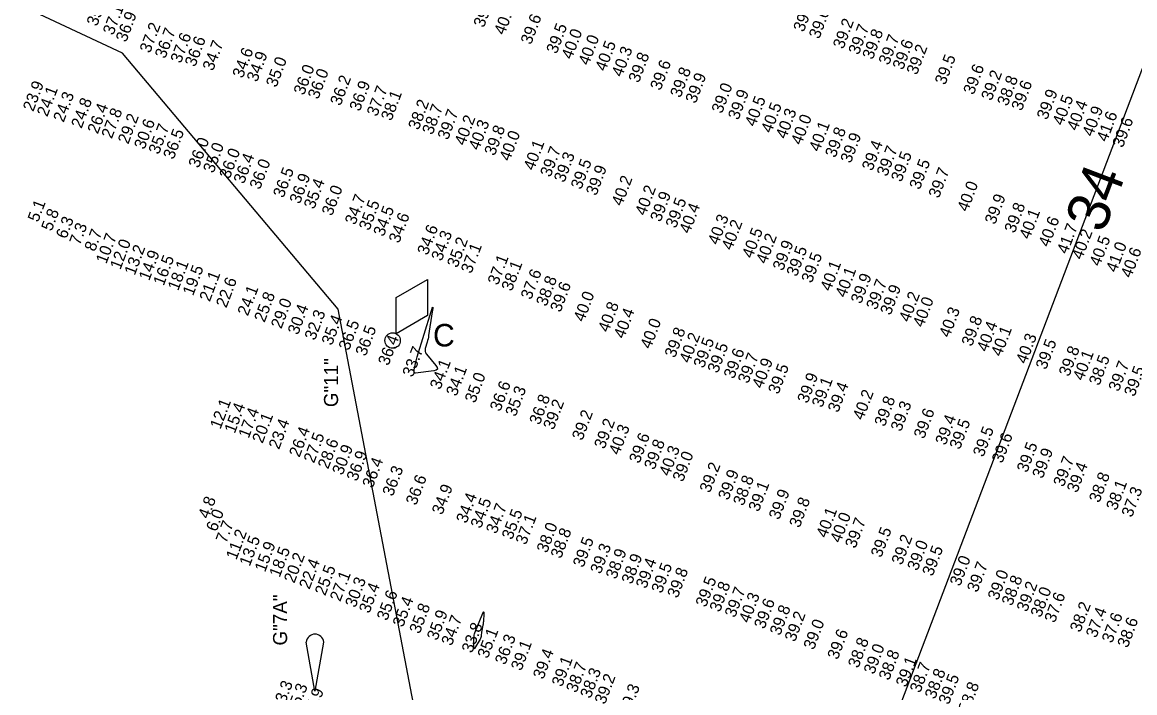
# Model space of a CAD drawing. Extents: x 510771 to 514171, y 1309813 to 1314213.
# Drawn here: x 511955 to 512904, y 1310850 to 1311422 of the extents above; entities that cross this region are included whole.
import ezdxf

# ---------------------------------------------------------------- set-up
doc = ezdxf.new("R2010")
doc.units = 0
for name, color, linetype in [('C-CHAN-CNTR', 7, 'Continuous'), ('C-CHAN-WIDE', 7, 'Continuous'), ('V-CHAN-NAID', 7, 'Continuous'), ('V-CHAN-TEXT', 7, 'Continuous'), ('V-TOPO-MAJR', 7, 'Continuous'), ('V-TOPO-SOUN', 7, 'Continuous')]:
    doc.layers.add(name, color=color, linetype=linetype)

msp = doc.modelspace()

# ---------------------------------------------------------------- linework, layer by layer
at = {"layer": 'C-CHAN-CNTR'}
msp.add_line((512571.8, 1310492.84), (513203.85, 1312154.97), dxfattribs=at)
at = {"layer": 'C-CHAN-WIDE'}
for p, q in [((512040.63, 1311395.58), (511536.45, 1311632.64)), ((512224.55, 1311177.34), (512040.63, 1311395.58)), ((512295.17, 1310807.21), (512224.55, 1311177.34))]:
    msp.add_line(p, q, dxfattribs=at)
at = {"layer": 'V-CHAN-NAID'}
for p, q in [((512274.08, 1311187.33), (512300.8, 1311202.76)), ((512300.8, 1311202.76), (512300.8, 1311171.9)), ((512274.08, 1311156.46), (512274.08, 1311187.33)), ((512300.8, 1311171.9), (512274.08, 1311156.46)), ((512204.75, 1310851.65), (512197.35, 1310893.6)), ((512212.14, 1310893.6), (512204.75, 1310851.65))]:
    msp.add_line(p, q, dxfattribs=at)
msp.add_circle((512270.91, 1311150.67), 6.6, dxfattribs=at)
msp.add_arc((512204.75, 1310893), 7.42, 4.64421, 175.35452, dxfattribs=at)
at = {"layer": 'V-TOPO-MAJR'}
for points in [[(512289.21, 1311125.08), (512289.22, 1311125.35), (512289.27, 1311125.63), (512290.76, 1311132.13), (512291.04, 1311133.3), (512291.34, 1311134.47), (512291.66, 1311135.63), (512292, 1311136.79), (512303.69, 1311175.4), (512304.61, 1311178.18), (512305.09, 1311179.06), (512305.14, 1311178.05), (512304.77, 1311175.15), (512301.65, 1311154.86), (512301.41, 1311153.47), (512301.13, 1311152.08), (512300.79, 1311150.71), (512300.42, 1311149.34), (512298.81, 1311143.91), (512298.57, 1311142.58), (512298.66, 1311141.33), (512299.08, 1311140.14), (512299.82, 1311139.02), (512307.92, 1311129.33), (512309.05, 1311127.56), (512309.12, 1311126.22), (512308.14, 1311125.29), (512306.11, 1311124.78), (512290.37, 1311122.95), (512290.11, 1311122.96), (512289.9, 1311123.04), (512289.74, 1311123.2), (512289.63, 1311123.44), (512289.3, 1311124.53), (512289.24, 1311124.8)], [(512348.16, 1310909.57), (512348.05, 1310908.84), (512347.91, 1310908.12), (512347.29, 1310905.23), (512347.15, 1310904.51), (512347.02, 1310903.78), (512346.91, 1310903.05), (512346.81, 1310902.32), (512346.44, 1310899.05), (512346.31, 1310898.28), (512346.11, 1310897.53), (512345.82, 1310896.8), (512345.46, 1310896.11), (512340.79, 1310888.09), (512340.6, 1310887.84), (512340.46, 1310887.77), (512340.37, 1310887.89), (512340.31, 1310888.2), (512340.19, 1310889.83), (512340.16, 1310890.24), (512340.14, 1310890.64), (512340.14, 1310891.05), (512340.14, 1310891.46), (512340.28, 1310897.33), (512340.36, 1310898.43), (512340.53, 1310899.52), (512340.79, 1310900.58), (512341.16, 1310901.63), (512347.76, 1310918.15), (512348.21, 1310919.12), (512348.5, 1310919.41), (512348.65, 1310919.02), (512348.66, 1310917.96), (512348.3, 1310911.04), (512348.25, 1310910.3)]]:
    msp.add_lwpolyline(points, close=True, dxfattribs=at)

# ---------------------------------------------------------------- texts
at = {"layer": 'V-CHAN-NAID'}
for s, height, rotation, p in [('C', 19.2, 0.00274, (512305.37, 1311145.61)), ('G"11"', 12, 90, (512224.42, 1311093.92)), ('G"7A"', 12, 90, (512180.97, 1310890.68))]:
    msp.add_text(s, height=height, rotation=rotation, dxfattribs=at).set_placement(p)
at = {"layer": 'V-CHAN-TEXT'}
msp.add_text('34', height=36, rotation=69.17989, dxfattribs=at).set_placement((512876.96, 1311241.2))
at = {"layer": 'V-TOPO-SOUN'}
for s, p in [('35.9 ', (512018.87, 1311418.05)), ('39.4 ', (512348.69, 1311416.85)), ('37.1 ', (512032.73, 1311410.45)), ('40.0 ', (512366.23, 1311410.57)), ('39.2 ', (512621.42, 1311413.09)), ('39.6 ', (512634.68, 1311407.22)), ('36.9 ', (512043.73, 1311404.45)), ('39.6 ', (512388.94, 1311402.35)), ('39.2 ', (512655.22, 1311398.6)), ('37.2 ', (512064.09, 1311395.15)), ('36.7 ', (512077.02, 1311390.43)), ('37.6 ', (512090.34, 1311386.47)), ('39.5 ', (512410.81, 1311394.43)), ('40.0 ', (512423.7, 1311389.77)), ('39.7 ', (512668.35, 1311393.66)), ('39.8 ', (512680.27, 1311389.6)), ('36.6 ', (512102.58, 1311383.43)), ('34.7 ', (512117.73, 1311379.88)), ('40.0 ', (512438.09, 1311384.68)), ('40.5 ', (512452.43, 1311379.61)), ('39.7 ', (512694.1, 1311384.9)), ('39.6 ', (512706.04, 1311380.76)), ('34.6 ', (512143.16, 1311373.72)), ('34.9 ', (512155.33, 1311370.47)), ('40.3 ', (512466.48, 1311374.76)), ('39.8 ', (512480.84, 1311369.78)), ('39.2 ', (512717.94, 1311376.49)), ('39.5 ', (512742.1, 1311367.93)), ('35.0 ', (512171.78, 1311365.89)), ('36.0 ', (512195.35, 1311359.27)), ('39.6 ', (512499.36, 1311363.27)), ('39.6 ', (512766.35, 1311359.61)), ('36.0 ', (512207.45, 1311355.78)), ('36.2 ', (512226.51, 1311350.24)), ('39.8 ', (512516.41, 1311357.08)), ('39.9 ', (512529.4, 1311352.2)), ('39.2 ', (512781.58, 1311354.53)), ('38.8 ', (512795.24, 1311349.95)), ('23.9 ', (511964.54, 1311345.34)), ('24.1 ', (511976.47, 1311340.89)), ('36.9 ', (512242.91, 1311345.49)), ('37.7 ', (512257.7, 1311341.12)), ('39.0 ', (512551.72, 1311343.62)), ('39.6 ', (512807.32, 1311345.86)), ('24.3 ', (511990.39, 1311336.12)), ('24.8 ', (512005.68, 1311330.96)), ('38.1 ', (512269.84, 1311337.29)), ('38.2 ', (512293.05, 1311329.56)), ('39.9 ', (512565.75, 1311338.1)), ('40.5 ', (512580.06, 1311332.38)), ('39.9 ', (512829.01, 1311338.23)), ('40.5 ', (512842.4, 1311333.38)), ('26.4 ', (512019.54, 1311326.25)), ('27.8 ', (512031.47, 1311322.2)), ('38.7 ', (512304.94, 1311325.5)), ('39.7 ', (512318.09, 1311321.07)), ('40.5 ', (512593.81, 1311326.94)), ('40.3 ', (512606.34, 1311321.92)), ('40.4 ', (512854.66, 1311328.87)), ('40.9 ', (512867.81, 1311323.95)), ('29.2 ', (512045.51, 1311317.52)), ('30.6 ', (512059.34, 1311312.99)), ('40.2 ', (512332.49, 1311316.23)), ('40.3 ', (512344.48, 1311312.25)), ('40.0 ', (512619.36, 1311316.83)), ('41.6 ', (512880.02, 1311319.4)), ('39.6 ', (512893.52, 1311314.46)), ('35.7 ', (512071.59, 1311308.78)), ('36.5 ', (512084.13, 1311304.48)), ('39.8 ', (512357.93, 1311307.61)), ('40.0 ', (512370.72, 1311302.99)), ('40.1 ', (512634.76, 1311311.01)), ('39.8 ', (512648.52, 1311305.94)), ('39.9 ', (512661.56, 1311301.23)), ('36.0 ', (512105.65, 1311297.14)), ('35.0 ', (512118.18, 1311292.81)), ('40.1 ', (512391.33, 1311295.02)), ('39.4 ', (512679.91, 1311294.68)), ('36.0 ', (512131.98, 1311287.94)), ('36.4 ', (512144.14, 1311283.64)), ('39.7 ', (512405.54, 1311289.43)), ('39.3 ', (512417.3, 1311284.73)), ('39.7 ', (512692.54, 1311289.99)), ('39.5 ', (512704.73, 1311285.22)), ('36.0 ', (512157.76, 1311278.81)), ('39.5 ', (512431.7, 1311278.87)), ('39.9 ', (512444.59, 1311273.58)), ('39.5 ', (512720.36, 1311278.7)), ('36.5 ', (512177.82, 1311271.65)), ('36.9 ', (512191.81, 1311266.55)), ('40.2 ', (512466.45, 1311264.7)), ('39.7 ', (512736.68, 1311271.41)), ('35.4 ', (512204.05, 1311262.09)), ('36.0 ', (512219.31, 1311256.38)), ('40.2 ', (512486.47, 1311256.47)), ('40.0 ', (512761.18, 1311259.89)), ('34.7 ', (512239.05, 1311248.64)), ('35.5 ', (512251.01, 1311243.82)), ('39.9 ', (512499.37, 1311251.15)), ('39.5 ', (512512.49, 1311245.84)), ('39.9 ', (512784.65, 1311248.98)), ('5.1', (511968.66, 1311251.04)), ('5.8', (511980.2, 1311243.36)), ('34.5 ', (512263.3, 1311238.72)), ('40.4 ', (512524.16, 1311241.22)), ('39.8 ', (512801.39, 1311241.67)), ('40.1 ', (512814.02, 1311236.38)), ('6.3', (511992.71, 1311236.78)), ('34.6 ', (512276.44, 1311233.04)), ('40.3 ', (512548.52, 1311231.62)), ('40.2 ', (512560.2, 1311227.05)), ('40.6 ', (512830.46, 1311229.8)), ('7.3', (512004.21, 1311231.37)), ('8.7', (512017.02, 1311225.96)), ('10.7 ', (512026.77, 1311215.42)), ('34.6 ', (512300.77, 1311222.79)), ('34.3 ', (512312.73, 1311217.82)), ('40.5 ', (512577.63, 1311220.15)), ('40.2 ', (512589.61, 1311215.36)), ('41.7 ', (512846.18, 1311223.79)), ('40.2 ', (512858.73, 1311219.03)), ('12.0 ', (512038.81, 1311210.5)), ('35.2 ', (512326.16, 1311212.15)), ('39.9 ', (512603.79, 1311209.52)), ('40.5 ', (512873.94, 1311213.36)), ('41.0 ', (512887.99, 1311208.11)), ('13.2 ', (512051.02, 1311205.67)), ('14.9 ', (512063.35, 1311201.08)), ('16.5 ', (512075.68, 1311196.76)), ('37.1 ', (512338, 1311207.15)), ('39.5 ', (512615.53, 1311204.57)), ('39.5 ', (512628.28, 1311199.08)), ('40.6 ', (512900.58, 1311203.42)), ('18.1 ', (512088.05, 1311192.6)), ('19.5 ', (512100.77, 1311188.29)), ('37.1 ', (512360.78, 1311197.32)), ('38.1 ', (512372.54, 1311192.12)), ('40.1 ', (512644.35, 1311192.14)), ('21.1 ', (512114.99, 1311183.22)), ('22.6 ', (512129.17, 1311177.95)), ('37.6 ', (512389.01, 1311184.9)), ('38.8 ', (512402.09, 1311179.19)), ('40.1 ', (512657.18, 1311186.67)), ('39.9 ', (512670.39, 1311181.34)), ('24.1 ', (512147.49, 1311171.05)), ('39.6 ', (512414.05, 1311174.13)), ('39.7 ', (512683.54, 1311176.24)), ('39.9 ', (512695.5, 1311171.71)), ('25.8 ', (512161.74, 1311165.56)), ('29.0 ', (512176, 1311160.08)), ('40.0 ', (512434, 1311165.97)), ('40.2 ', (512711.51, 1311165.74)), ('40.0 ', (512723.31, 1311161.26)), ('30.4 ', (512190.29, 1311154.93)), ('32.3 ', (512204.68, 1311150.22)), ('40.8 ', (512454.91, 1311157.09)), ('40.4 ', (512468.27, 1311151.68)), ('40.3 ', (512745.69, 1311152.57)), ('35.4 ', (512219.17, 1311145.93)), ('36.5 ', (512233.7, 1311141.59)), ('40.0 ', (512490.91, 1311142.91)), ('39.8 ', (512764.84, 1311145.09)), ('40.4 ', (512777.85, 1311140.42)), ('36.5 ', (512248.05, 1311136.76)), ('39.8 ', (512511.7, 1311135.26)), ('40.2 ', (512524.2, 1311130.79)), ('40.1 ', (512789.93, 1311136.42)), ('40.3 ', (512811.23, 1311130.13)), ('36.4 ', (512267.34, 1311128.63)), ('39.5 ', (512536.25, 1311126.5)), ('39.5 ', (512548.21, 1311122.26)), ('39.5 ', (512828.09, 1311125.26)), ('33.7 ', (512288.09, 1311118.88)), ('39.6 ', (512562.02, 1311117.48)), ('39.7 ', (512574.09, 1311113.41)), ('39.8 ', (512847.78, 1311119.42)), ('40.1 ', (512859.76, 1311115.82)), ('38.5 ', (512873.46, 1311111.63)), ('34.1 ', (512311.56, 1311108.21)), ('40.9 ', (512586.21, 1311109.11)), ('39.5 ', (512599.89, 1311104.27)), ('39.7 ', (512890.08, 1311106.56)), ('39.5 ', (512903.44, 1311102.21)), ('34.1 ', (512325.33, 1311102.56)), ('35.0 ', (512341.28, 1311096.78)), ('39.9 ', (512624.8, 1311096.53)), ('36.6 ', (512362.68, 1311089.6)), ('35.3 ', (512375.84, 1311085.22)), ('39.1 ', (512637.19, 1311092.89)), ('39.4 ', (512650.81, 1311088.65)), ('12.1 ', (512124.09, 1311074.51)), ('36.8 ', (512396.31, 1311078.13)), ('39.2 ', (512408.18, 1311073.93)), ('40.2 ', (512672.07, 1311082.19)), ('39.8 ', (512690.54, 1311076.68)), ('15.4 ', (512136.32, 1311070.92)), ('17.4 ', (512148.21, 1311066.73)), ('39.2 ', (512432.69, 1311064.9)), ('39.3 ', (512704.41, 1311072.46)), ('39.6 ', (512724.09, 1311066.27)), ('20.1 ', (512160.04, 1311062.47)), ('23.4 ', (512174.08, 1311057.26)), ('39.2 ', (512451.58, 1311057.59)), ('39.4 ', (512742.48, 1311060.81)), ('39.5 ', (512754.56, 1311057.17)), ('26.4 ', (512191.5, 1311050.55)), ('27.5 ', (512203.89, 1311045.56)), ('40.3 ', (512464.1, 1311052.51)), ('39.6 ', (512481.36, 1311045.32)), ('39.5 ', (512774.6, 1311050.76)), ('39.6 ', (512790.68, 1311045.43)), ('28.6 ', (512215.95, 1311040.53)), ('30.9 ', (512228.24, 1311035.32)), ('39.8 ', (512494.15, 1311039.88)), ('39.5 ', (512811.97, 1311037.45)), ('36.9 ', (512240.48, 1311030.07)), ('40.3 ', (512506.92, 1311034.46)), ('39.0 ', (512518.46, 1311029.58)), ('39.9 ', (512825.14, 1311032.36)), ('39.7 ', (512843.07, 1311025.31)), ('36.4 ', (512253.92, 1311024.34)), ('36.3 ', (512271.04, 1311017.26)), ('39.2 ', (512541.5, 1311020.22)), ('39.4 ', (512854.67, 1311020.31)), ('36.6 ', (512290.99, 1311009.58)), ('39.9 ', (512557.25, 1311014.01)), ('38.8 ', (512570.04, 1311009.14)), ('38.8 ', (512873.55, 1311011.81)), ('34.9 ', (512313.24, 1311001.51)), ('39.1 ', (512583.11, 1311004.12)), ('38.1 ', (512888.14, 1311005.17)), ('37.3 ', (512901.27, 1310999.34)), ('4.8', (512113.93, 1310998.12)), ('34.4 ', (512333.94, 1310994.21)), ('34.5 ', (512346.2, 1310989.9)), ('39.9 ', (512600.51, 1310997.29)), ('39.8 ', (512617.96, 1310990.47)), ('6.0', (512120.76, 1310987.19)), ('34.7 ', (512359.38, 1310985.22)), ('35.5 ', (512372.83, 1310980.28)), ('40.1 ', (512640.91, 1310981.79)), ('7.7', (512129.01, 1310977.38)), ('37.1 ', (512384.59, 1310975.91)), ('38.0 ', (512402.57, 1310968.94)), ('40.0 ', (512652.77, 1310977.52)), ('39.7 ', (512665.53, 1310972.88)), ('11.2 ', (512137.69, 1310963.08)), ('38.8 ', (512414.46, 1310964.22)), ('39.5 ', (512687.48, 1310965.01)), ('13.5 ', (512149.07, 1310957.62)), ('15.9 ', (512162.15, 1310952.66)), ('39.5 ', (512433.49, 1310956.52)), ('39.3 ', (512448.29, 1310951.06)), ('39.2 ', (512705.15, 1310958.68)), ('39.0 ', (512718.54, 1310953.82)), ('18.5 ', (512174.56, 1310948.15)), ('20.2 ', (512187.09, 1310943.2)), ('38.9 ', (512461.47, 1310946.61)), ('38.9 ', (512474.92, 1310942.35)), ('39.5 ', (512731.35, 1310949.18)), ('39.0 ', (512754.84, 1310940.67)), ('22.4 ', (512200.02, 1310938)), ('25.5 ', (512213.45, 1310932.59)), ('39.4 ', (512487.09, 1310938.57)), ('39.5 ', (512500.36, 1310934.56)), ('39.7 ', (512769.51, 1310935.37)), ('27.1 ', (512226.25, 1310927.56)), ('30.3 ', (512239.24, 1310922.37)), ('39.8 ', (512513.95, 1310930.52)), ('39.5 ', (512538.08, 1310922.78)), ('39.0 ', (512787.17, 1310928.6)), ('38.8 ', (512799.06, 1310923.86)), ('35.4 ', (512251.08, 1310917.51)), ('39.8 ', (512549.95, 1310918.6)), ('39.7 ', (512562.89, 1310913.86)), ('39.2 ', (512811.82, 1310918.69)), ('38.0 ', (512823.68, 1310914.02)), ('35.6 ', (512266.25, 1310911.23)), ('35.4 ', (512279.77, 1310905.73)), ('40.3 ', (512574.99, 1310909.23)), ('39.6 ', (512587.95, 1310904.14)), ('37.6 ', (512835.54, 1310909.4)), ('35.8 ', (512294, 1310900.09)), ('35.9 ', (512308.97, 1310894.36)), ('39.8 ', (512601.32, 1310898.61)), ('39.2 ', (512614.04, 1310893.21)), ('38.2 ', (512857.28, 1310901.31)), ('37.4 ', (512870.88, 1310896.57)), ('34.7 ', (512321.28, 1310889.82)), ('33.8 ', (512338.64, 1310883.65)), ('39.0 ', (512630.1, 1310886.44)), ('37.6 ', (512884.43, 1310892.14)), ('38.6 ', (512897.68, 1310888.1)), ('35.1 ', (512352.06, 1310878.96)), ('39.6 ', (512650.45, 1310878.01)), ('36.3 ', (512366.98, 1310873.6)), ('39.1 ', (512380.65, 1310868.56)), ('38.8 ', (512668.03, 1310870.85)), ('39.0 ', (512681.42, 1310865.48)), ('39.4 ', (512399.44, 1310861.26)), ('38.8 ', (512694.23, 1310860.36)), ('39.1 ', (512415.41, 1310854.88)), ('38.7 ', (512427.69, 1310849.79)), ('39.1 ', (512708.84, 1310854.58)), ('38.7 ', (512720.75, 1310849.71)), ('38.3 ', (512439.69, 1310844.97)), ('39.2 ', (512451.98, 1310839.93)), ('38.8 ', (512733.49, 1310844.39)), ('39.5 ', (512745.18, 1310839.73)), ('13.3 ', (512176.9, 1310834.19)), ('15.3 ', (512189.52, 1310831.77)), ('17.9 ', (512203.3, 1310827.81)), ('39.3 ', (512472.75, 1310831.31)), ('38.8 ', (512762.13, 1310833.06))]:
    msp.add_text(s, height=9.996, rotation=69.1797, dxfattribs=at).set_placement(p)

doc.saveas('drawing.dxf')
